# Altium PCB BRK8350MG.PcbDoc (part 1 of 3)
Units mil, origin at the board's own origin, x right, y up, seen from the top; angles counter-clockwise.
Board outline 8858.27 x 5511.81 mil, 6 copper layers (L1-TOP, L2-GND, L3-PWR, L4-PWR, L5-GND, L6-BOT), stack 81.526 mil thick; 49 components, 350 nets, 1087 pads, 250 vias.
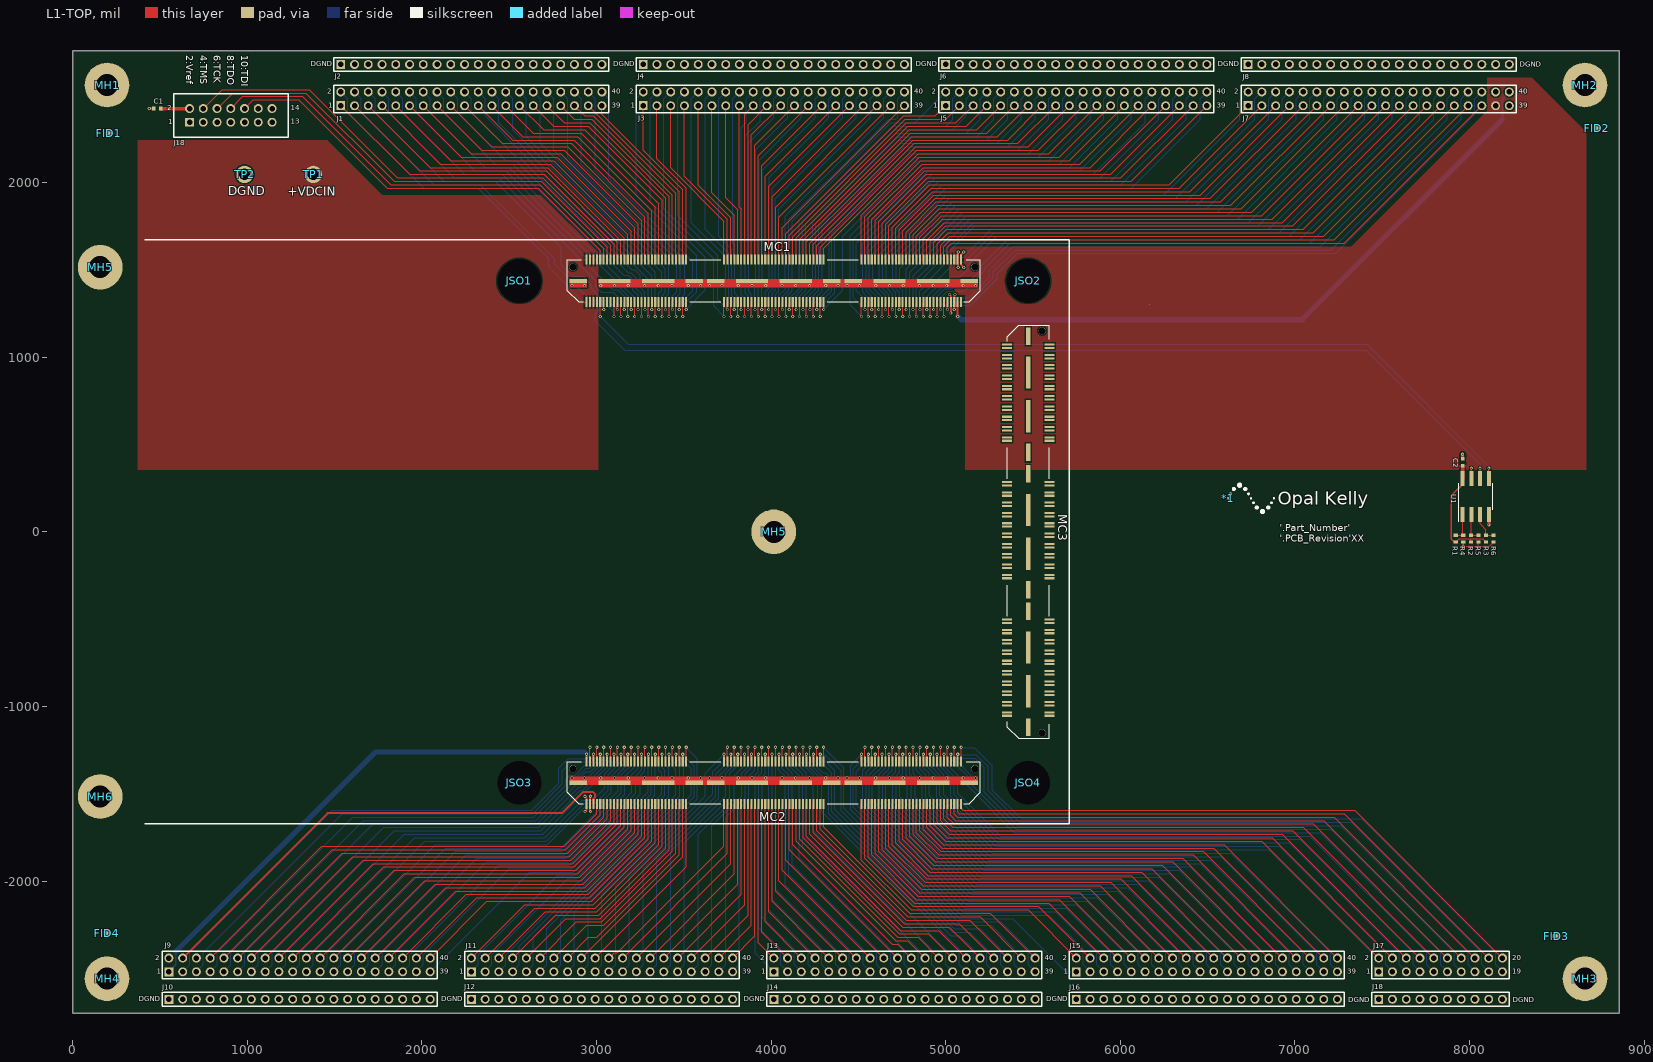
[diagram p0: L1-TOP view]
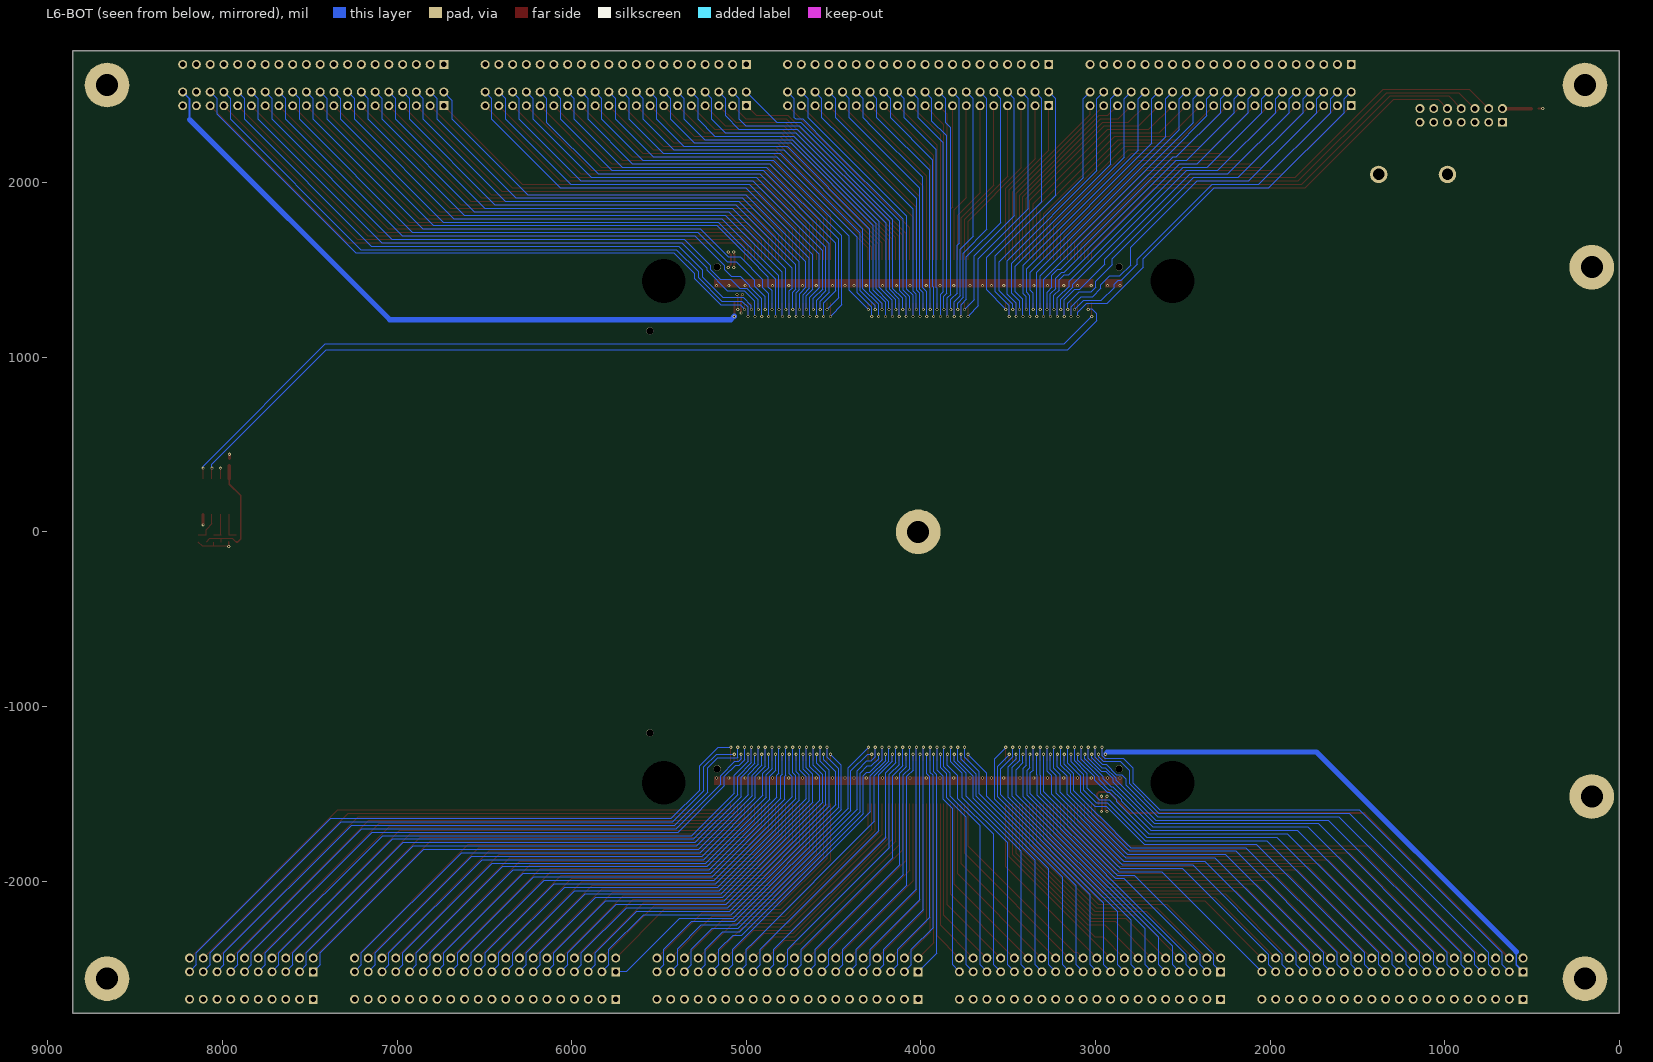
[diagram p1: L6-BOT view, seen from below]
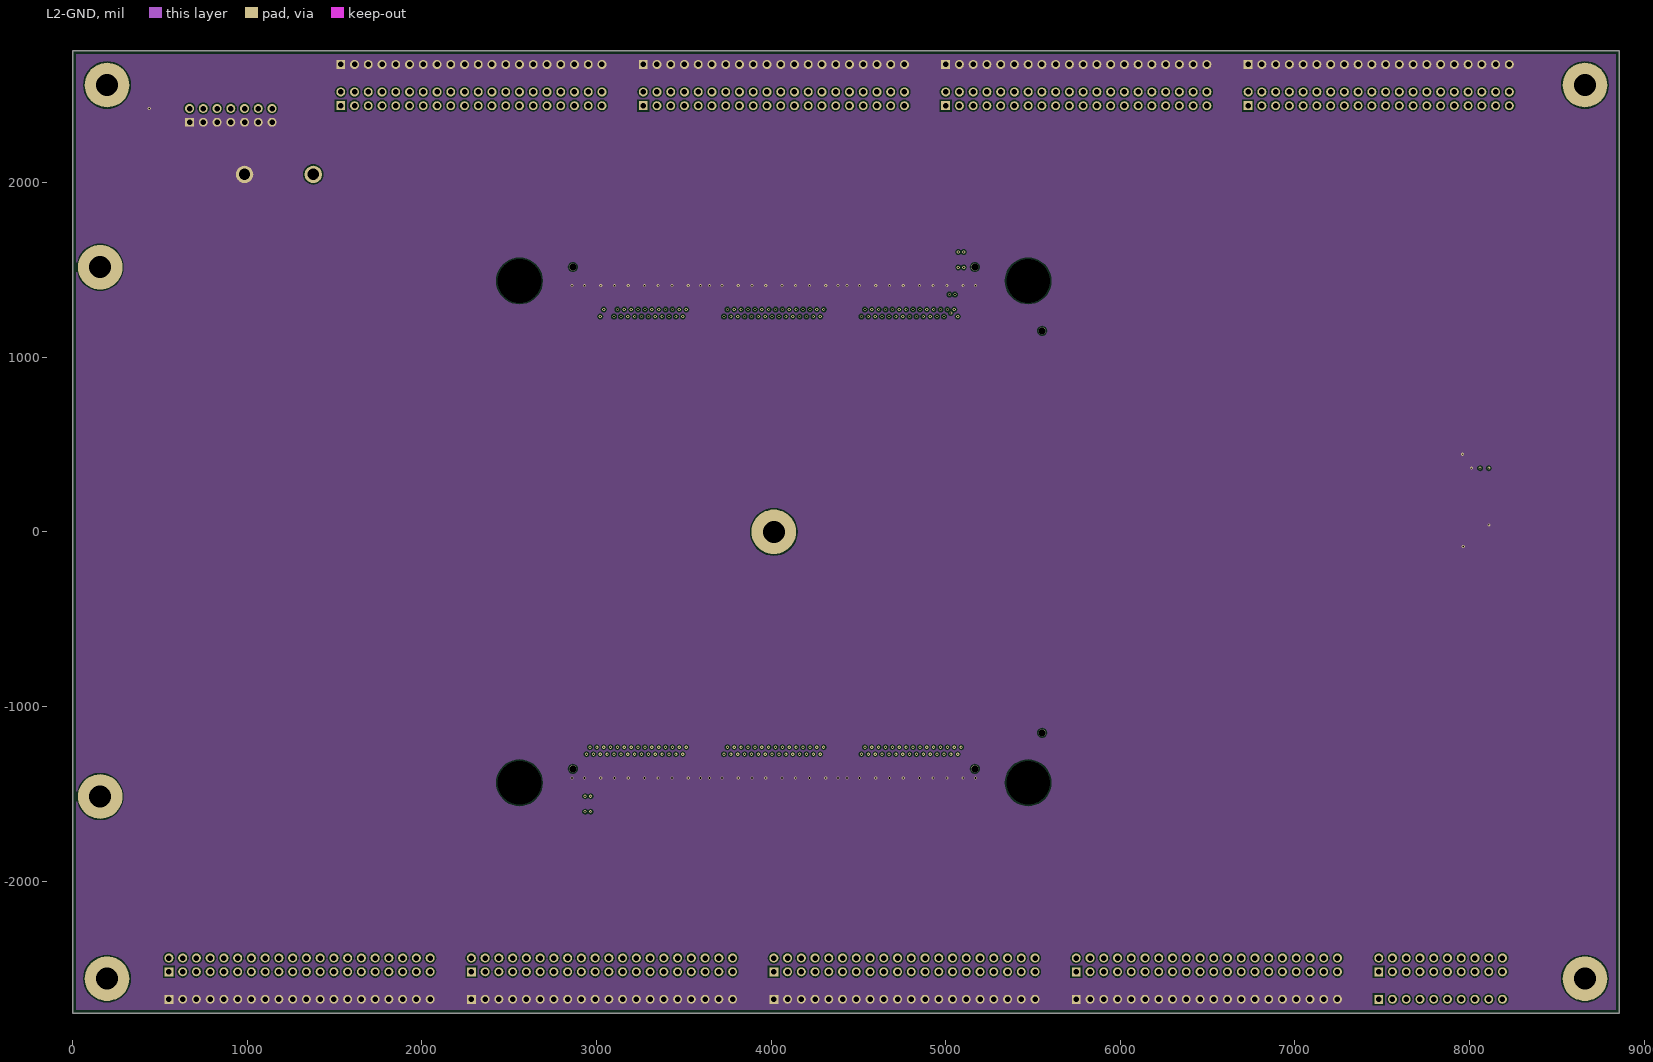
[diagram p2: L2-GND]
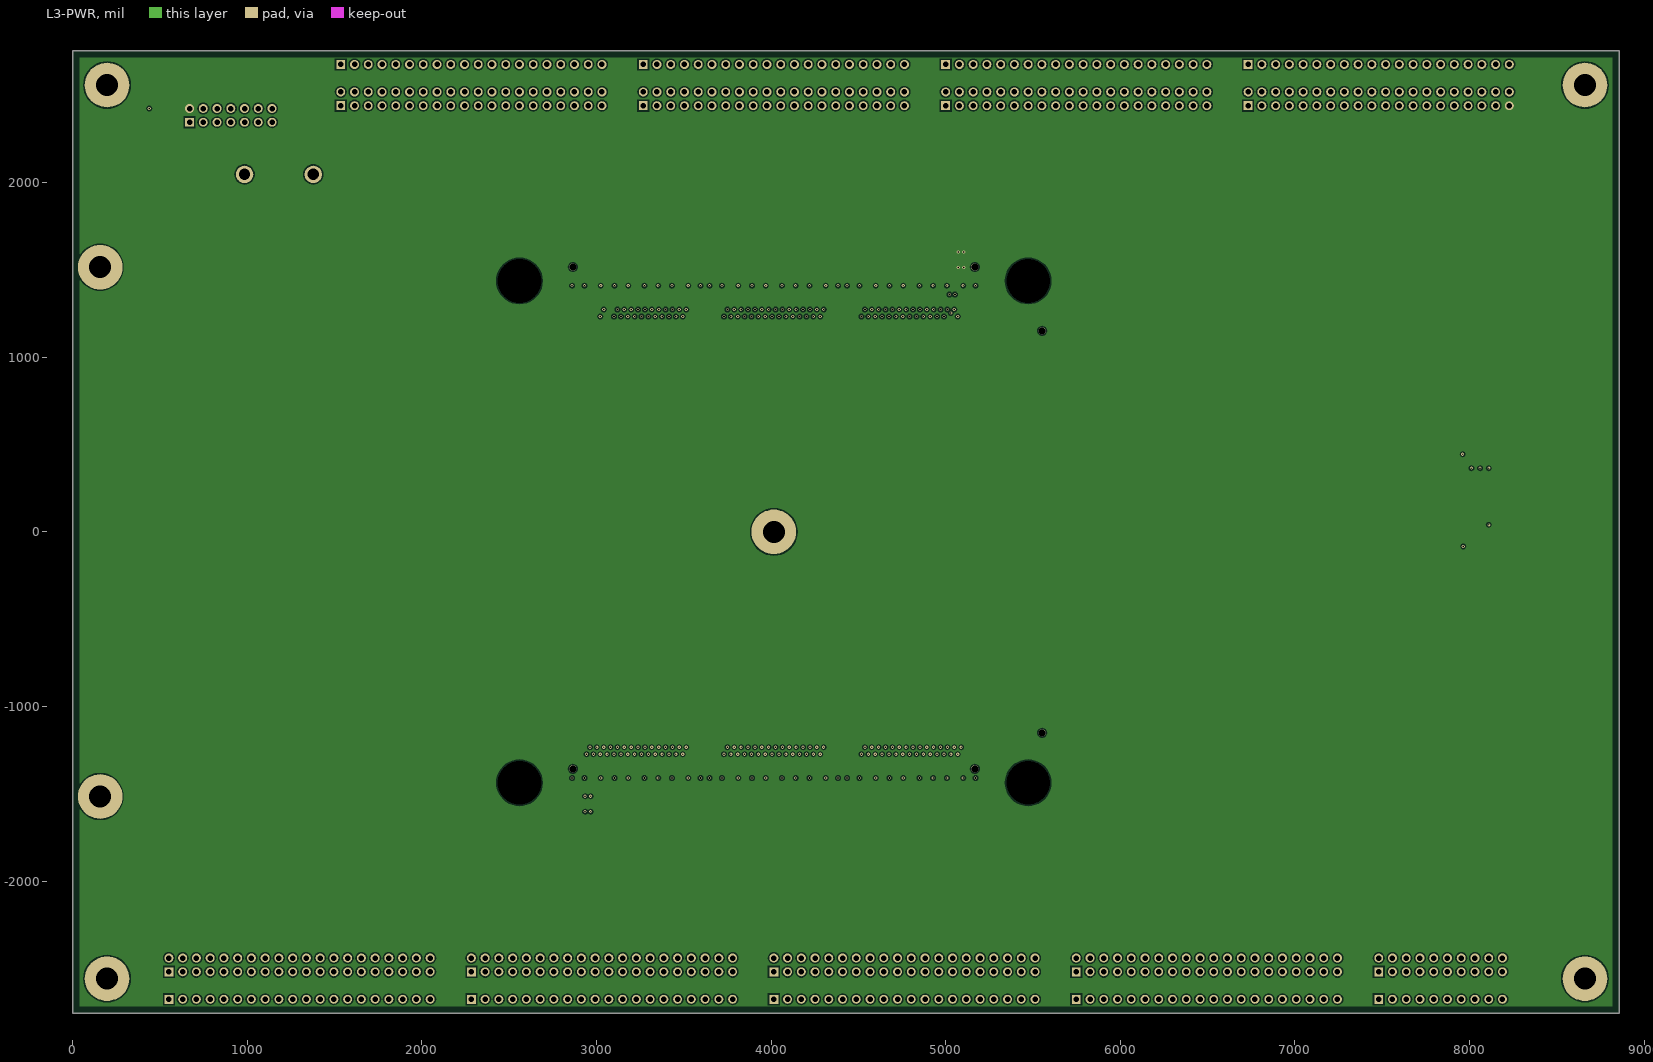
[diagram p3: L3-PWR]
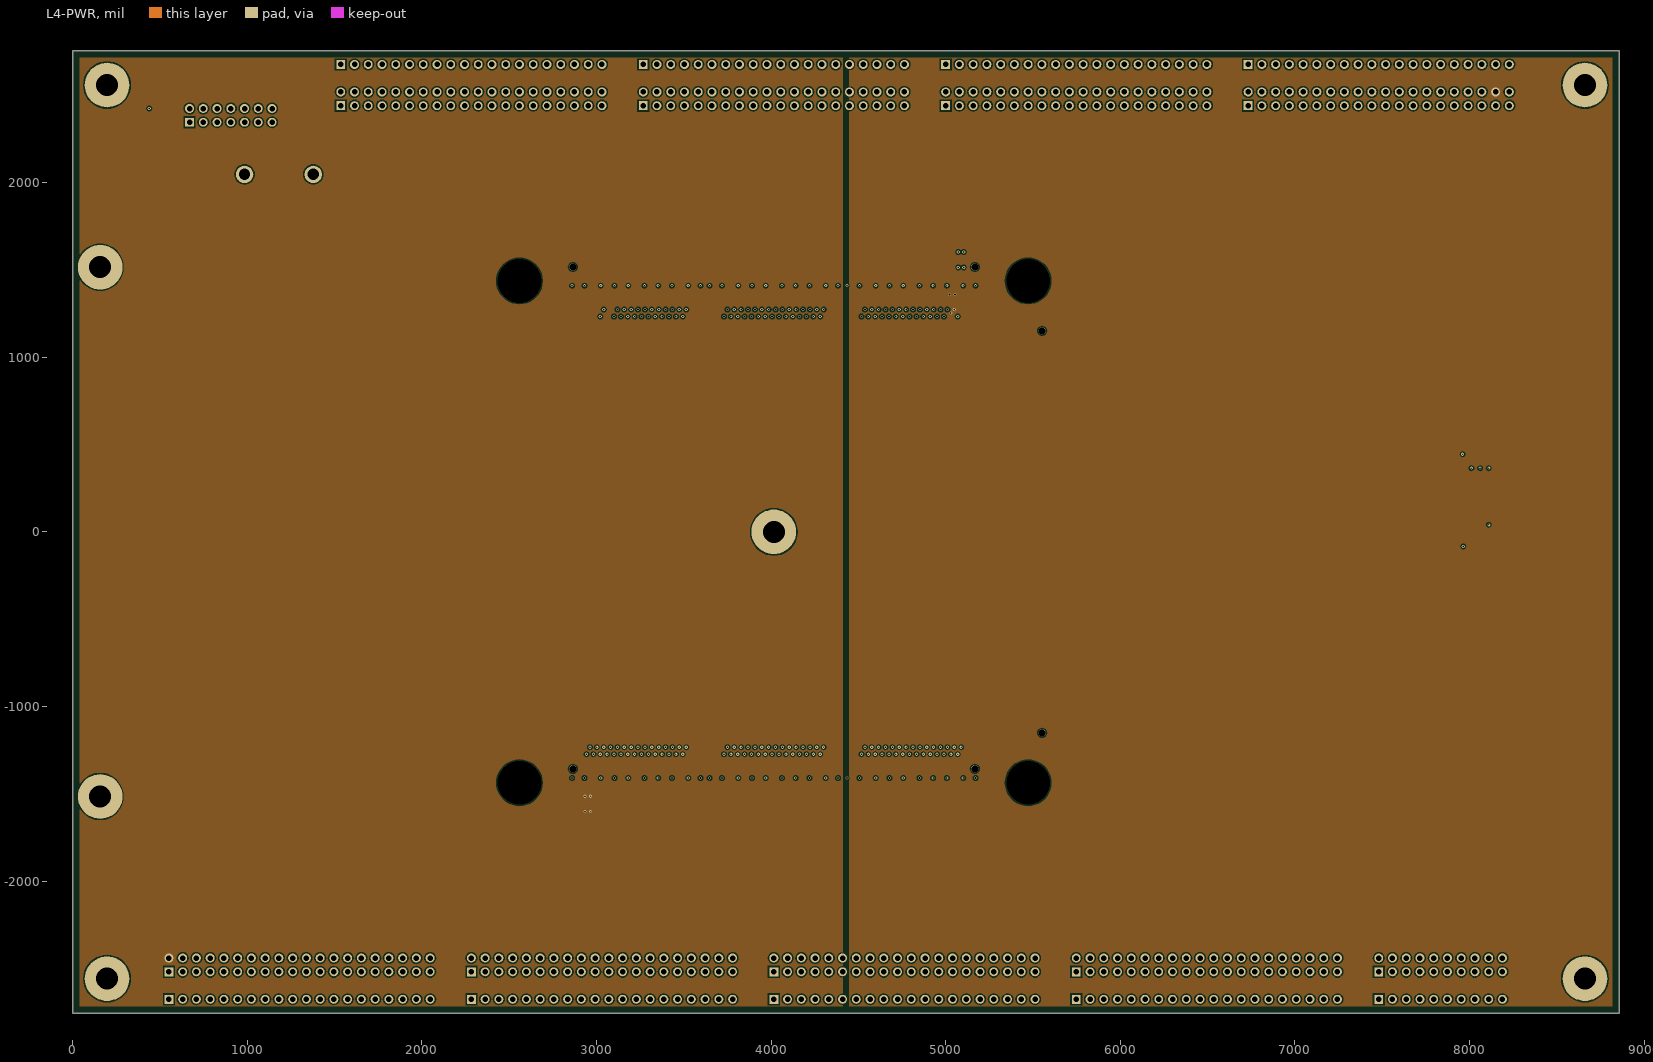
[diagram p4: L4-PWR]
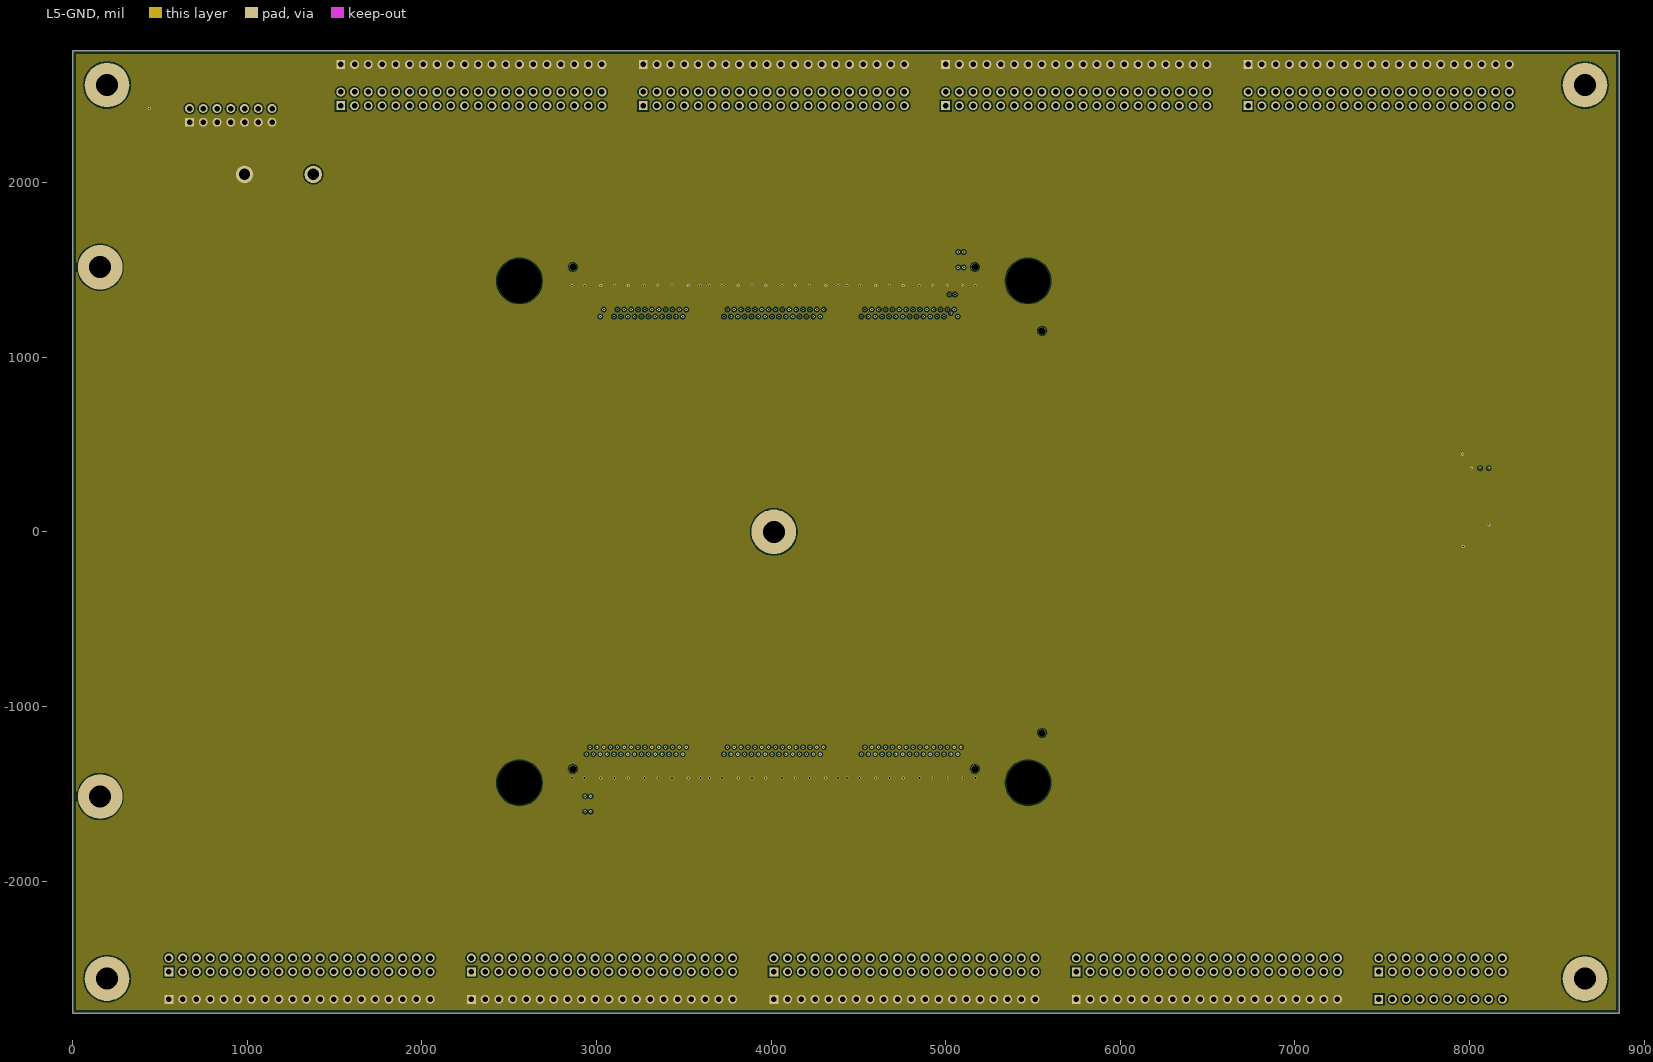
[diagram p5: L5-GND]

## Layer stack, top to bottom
Top Solder Mask: solder mask 0.8, Solder Resist, Dk 3.5
L1-TOP: signal copper 0.7
Dielectric 1-2: core 4.57, IT180A, Dk 4.07
L2-GND: signal copper 1.4
Dielectric 2: prepreg 20, IT180A, Dk 4.27
L3-PWR: signal copper 1.378
Dielectric 3: core 20, IT180A, Dk 4.02
L4-PWR: signal copper 1.378
Dielectric 1: prepreg 20, IT180A, Dk 4.27
L5-GND: signal copper 1.4
Dielectric 4: core 10, IT180A, Dk 4.07
L6-BOT: signal copper 0.7
Bottom Solder Mask: solder mask 0.8, Solder Resist, Dk 3.5

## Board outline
0,-2755.91 0,2755.91 8858.27,2755.91 8858.27,-2755.91

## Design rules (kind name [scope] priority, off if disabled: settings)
Clearance [All] p1: gap=5 ignorepadtopadclearanceinfootprint=FALSE except(4.5: SMDPad-Via Via-Via; 7: Via-Poly; 8: Arc-Poly SMDPad-Poly THPad-Poly Via-Fill Via-Region Fill-Poly Poly-Region Poly-Text Poly-Hole; 10: Track-Poly; 15: Poly-Poly)
DiffPairsRouting 100ohm_Diff [InDifferentialPairClass('100ohm_Diff')] p1: maxlimit=10 minlimit=8.4 mostfreqgap=8.4 toplayer_maxgap=8.4 toplayer_minwidth=4.2 toplayer_maxwidth=4.2 toplayer_prefwidth=4.2 midlayer1_mingap=10 midlayer1_prefgap=10 midlayer1_minwidth=15 midlayer1_maxwidth=15 midlayer1_prefwidth=15 midlayer2_maxgap=8.4 midlayer2_minwidth=4.2 midlayer2_maxwidth=4.2 midlayer2_prefwidth=4.2 midlayer3_maxgap=8.4 midlayer3_minwidth=4.2 midlayer3_maxwidth=4.2 midlayer3_prefwidth=4.2 midlayer5_mingap=10 midlayer5_prefgap=10 midlayer5_minwidth=15 midlayer5_maxwidth=15 midlayer5_prefwidth=15 bottomlayer_maxgap=8.4 bottomlayer_minwidth=4.2 bottomlayer_maxwidth=4.2 bottomlayer_prefwidth=4.2 maxuncoupledlength=350
FabricationTestPointUsage TestPointUsage [All] p1: valid=0 allowmultiple=FALSE
FabricationTestpoint Testpoint [All] p1: side=3 testpointundercomponent=TRUE minsize=40 maxsize=100 preferedsize=60 minholesize=0 maxholesize=40 preferedholesize=32 testpointgrid=1 allowsidetop=TRUE allowsidebottom=TRUE usegrid=TRUE gridtolerance=0.01
HoleSize [All] p1: absolutevalues=TRUE maxlimit=500 minlimit=8 maxpercent=80.000 minpercent=20.000
MatchedLengths okMatched_PortA [InxSignalClass('xSignals_PORTA')] p1: tolerance=1000 checknetsindiffpair=FALSE checkdiffpairvsdiffpair=TRUE checkxsignals=TRUE checkothers=TRUE
MatchedLengths okMatched_PortB [InxSignalClass('xSignals_PORTB')] p2: tolerance=1000 checknetsindiffpair=FALSE checkdiffpairvsdiffpair=TRUE checkxsignals=TRUE checkothers=TRUE
MatchedLengths okMatched_PortC [InxSignalClass('xSignals_PORTC')] p3: tolerance=1000 checknetsindiffpair=FALSE checkdiffpairvsdiffpair=TRUE checkxsignals=TRUE checkothers=TRUE
MatchedLengths okMatched_PortD [InxSignalClass('xSignals_PORTD')] p4: tolerance=1000 checknetsindiffpair=FALSE checkdiffpairvsdiffpair=TRUE checkxsignals=TRUE checkothers=TRUE
MatchedLengths okMatched_PortE [InxSignalClass('xSignals_PORTE')] p5: tolerance=1000 checknetsindiffpair=FALSE checkdiffpairvsdiffpair=TRUE checkxsignals=TRUE checkothers=TRUE
MatchedLengths okMatched_PortF [InxSignalClass('xSignals_PORTF')] p6: tolerance=1000 checknetsindiffpair=FALSE checkdiffpairvsdiffpair=TRUE checkxsignals=TRUE checkothers=TRUE
MatchedLengths okMatched_100ohm_Diff [InxSignalClass('xSignals_100ohm_Diff')] p7: tolerance=5 checknetsindiffpair=TRUE checkdiffpairvsdiffpair=FALSE checkxsignals=FALSE checkothers=FALSE
MinimumAnnularRing [All] p1: minimumring=4
MinimumSolderMaskSliver [All] p1: minsoldermaskwidth=1.9
PlaneClearance [All] p1: clearance=12
PlaneConnect [All] p1: planeconnectstyle=Direct reliefexpansion=20 reliefentries=4 reliefconductorwidth=10 reliefairgap=10
PolygonConnect "Via Connect" [IsVia] p1: connectstyle=Direct reliefconductorwidth=10 reliefentries=4 polygonreliefangle="90 Angle" airgapwidth=10
PolygonConnect [All] p2: thpad.connectstyle=Direct thpad.reliefconductorwidth=12 thpad.reliefentries=4 thpad.polygonreliefangle="90 Angle" thpad.airgapwidth=10 smdpad.connectstyle=Relief smdpad.reliefconductorwidth=12 smdpad.reliefentries=4 smdpad.polygonreliefangle="90 Angle" smdpad.airgapwidth=10 via.connectstyle=Direct via.reliefconductorwidth=12 via.reliefentries=4 via.polygonreliefangle="90 Angle" via.airgapwidth=10
RoutingVias [All] p1: holewidth=8 width=16 viastyle="Through Hole" minholewidth=8 minwidth=16 maxholewidth=50 maxwidth=100
SilkToSilkClearance [All] p1: silktosilkclearance=0.1
SilkToSolderMaskClearance SilkscreenOverComponentPads [IsPad] p1: minsilkscreentomaskgap=2 clearancetoexposedcopper=TRUE
SolderMaskExpansion [All] p1: expansion=2 istentingtop=FALSE
Width okWidth_50ohm [InNetClass('50ohm')] p1: maxlimit=10 minlimit=4.5 preferedwidth=4.6 toplayer_maxwidth=4.5 toplayer_prefwidth=4.5 midlayer1_minwidth=10 midlayer1_prefwidth=10 midlayer2_minwidth=4.6 midlayer2_maxwidth=4.6 midlayer3_minwidth=4.6 midlayer3_maxwidth=4.6 midlayer5_minwidth=10 midlayer5_prefwidth=10 bottomlayer_maxwidth=4.5 bottomlayer_prefwidth=4.5 minimp=50.000000 maximp=50.000000 favimp=50.000000
Width okWidth [All] p2: maxlimit=150 minlimit=4 preferedwidth=7.87 toplayer_prefwidth=5 midlayer1_prefwidth=5 midlayer2_prefwidth=5 midlayer3_prefwidth=5 midlayer5_minwidth=7.87 midlayer5_maxwidth=7.87 bottomlayer_prefwidth=5 minimp=50.000000 maximp=50.000000 favimp=50.000000
21 further rules are at their usual default settings.

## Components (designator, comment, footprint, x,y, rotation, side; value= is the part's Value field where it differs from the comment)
*1 "Opal Kelly Logo" okLogo-23x5 6617.7,192.24 r0 top
C1 "SM-0402, 10%, 10v" CAPC1005X06A#1 483.65,2424.44 r0 top value="0.1 u"
C2 "SM-0402, 10%, 10v" CAPC1005X06A#2 7961,399.08 r270 top value="0.1 u"
FID1 "FIDUCIAL" FID1MM/2MM-SS 207,2283 r90 top
FID2 "FIDUCIAL" FID1MM/2MM-SS 8730,2313 r90 top
FID3 "FIDUCIAL" FID1MM/2MM-SS 8496,-2316 r90 top
FID4 "FIDUCIAL" FID1MM/2MM-SS 195,-2298 r90 top
J1 "0877584016" HDR2X20-2MM 2283.46,2480.31 r0 top locked
J2 "Header, 20-Pin, Single Row" HDR1X20-2MM 2283.46,2677.17 r0 top locked
J3 "0877584016" HDR2X20-2MM 4015.75,2480.31 r0 top locked
J4 "Header, 20-Pin, Single Row" HDR1X20-2MM 4015.75,2677.17 r0 top locked
J5 "0877584016" HDR2X20-2MM 5748.03,2480.31 r0 top locked
J6 "Header, 20-Pin, Single Row" HDR1X20-2MM 5748.03,2677.17 r0 top locked
J7 "0877584016" HDR2X20-2MM 7480.31,2480.31 r0 top locked
J8 "Header, 20-Pin, Single Row" HDR1X20-2MM 7480.31,2677.17 r0 top locked
J9 "0877584016" HDR2X20-2MM 1299.21,-2480.32 r0 top locked
J10 "Header, 20-Pin, Single Row" HDR1X20-2MM 1299.21,-2677.17 r0 top locked
J11 "0877584016" HDR2X20-2MM 3031.5,-2480.32 r0 top locked
J12 "Header, 20-Pin, Single Row" HDR1X20-2MM 3031.5,-2677.17 r0 top locked
J13 "0877584016" HDR2X20-2MM 4763.78,-2480.32 r0 top locked
J14 "Header, 20-Pin, Single Row" HDR1X20-2MM 4763.78,-2677.17 r0 top locked
J15 "0877584016" HDR2X20-2MM 6496.06,-2480.32 r0 top locked
J16 "Header, 20-Pin, Single Row" HDR1X20-2MM 6496.06,-2677.17 r0 top locked
J17 "0877582016" HDR2X10-2MM 7834.65,-2480.32 r0 top locked
J18 "Header, 20-Pin, Single Row" HDR1X10-2MM 7834.65,-2677.17 r0 top locked
J18 "87831-1420" XILINX-JTAG 905.51,2385.31 r0 top
JSO1 "Jack Screw Standoff" JSO-0515-01 2559.06,1437.01 r0 top locked
JSO2 "Jack Screw Standoff" JSO-0515-01 5472.44,1437.01 r0 top locked
JSO3 "Jack Screw Standoff" JSO-0515-01 2559.06,-1437.01 r0 top locked
JSO4 "Jack Screw Standoff" JSO-0515-01 5472.44,-1437.01 r0 top locked
MC1 "QTH-090-01-F-D-A" QTH-090-01-X-D 4015.76,1437.02 r0 top locked
MC2 "QTH-090-01-F-D-A" QTH-090-01-X-D 4015.76,-1436.99 r0 top locked
MC3 "QTH-060-01-L-D-DP-A" QTH-060-01-X-D-DP-A 5472.46,0.02 r270 top locked
MH1 "MTG" MTG-3.2/6.5-PTH 196.85,2559.06 r0 top locked
MH2 "MTG" MTG-3.2/6.5-PTH 8661.42,2559.06 r0 top locked
MH3 "MTG" MTG-3.2/6.5-PTH 8661.42,-2559.06 r0 top locked
MH4 "MTG" MTG-3.2/6.5-PTH 196.85,-2559.06 r0 top locked
MH5 "MTG" MTG-3.2/6.5-PTH 4015.75,0 r0 top locked
MH5 "MTG" MTG-3.2/6.5-PTH 157.48,1515.75 r0 top locked
MH6 "MTG" MTG-3.2/6.5-PTH 157.48,-1515.75 r0 top locked
R1 "SM-0402, 1%, 1/16W" RESC1005X06A 7921.22,-38.49 r270 top value="10.0 k"
R2 "SM-0402, 1%, 1/16W" RESC1005X06A 8007.83,-38.49 r270 top value="10.0 k"
R3 "SM-0402, 1%, 1/16W" RESC1005X06A 8094.45,-38.49 r270 top value="10.0 k"
R4 "SM-0402, 1%, 1/16W" RESC1005X06A 7964.53,-38.49 r90 top value="10.0 k"
R5 "SM-0402, 1%, 1/16W" RESC1005X06A 8051.14,-38.49 r90 top value="10.0 k"
R6 "SM-0402, 1%, 1/16W" RESC1005X06A 8137.76,-38.49 r90 top value="10.0 k"
TP1 "+VDCIN" TP-PTH-65/100 1377.95,2047.24 r0 top
TP2 "DGND" TP-PTH-65/100 984.25,2047.24 r90 top
U1 "24FC256-I/SN" SO-G8 8035.96,202.42 r0 top locked

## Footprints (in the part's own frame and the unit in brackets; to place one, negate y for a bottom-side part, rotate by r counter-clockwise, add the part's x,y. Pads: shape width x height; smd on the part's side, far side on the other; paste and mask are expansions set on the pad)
CAPC1005X06A#1 [mm] "Chip Capacitor, 2-Leads, Body 1.00x0.50mm, OK custom footprint"
  rect 0.52x0.55 smd: 1(-0.51,0) 2(0.51,0)
CAPC1005X06A#2 [mm] "Chip Capacitor, 2-Leads, Body 1.00x0.50mm, OK custom footprint"
  rect 0.52x0.55 smd mask+0.051: 1(-0.51,0) 2(0.51,0)
FID1MM/2MM-SS [mm] "Fiducial 1mm copper, 2mm soldermask, single-side"
  round 1 smd paste-0.5 mask+0.5: FID?(0,0)
HDR1X10-2MM [mm] "2mm 1x20 Header"
  rect 1.3x1.3 hole 0.8: 1(-9,0)
  round 1.3 hole 0.8: 2(-7,0) 3(-5,0) 4(-3,0) 5(-1,0) 6(1,0) 7(3,0) 8(5,0) 9(7,0) 10(9,0)
  silkscreen extent -10,-1 10,1
HDR1X20-2MM [mm] "2mm 1x20 Header"
  rect 1.3x1.3 hole 0.8: 1(-19,0)
  round 1.3 hole 0.8: 2(-17,0) 3(-15,0) 4(-13,0) 5(-11,0) 6(-9,0) 7(-7,0) 8(-5,0) 9(-3,0) 10(-1,0) 11(1,0) 12(3,0) 13(5,0) 14(7,0) 15(9,0) 16(11,0) 17(13,0) 18(15,0) 19(17,0) 20(19,0)
  silkscreen extent -20,-1 20,1
HDR2X10-2MM [mm] "2mm 2x10 header"
  rect 1.3x1.3 hole 0.8: 1(-9,-1)
  round 1.3 hole 0.8: 2(-9,1) 3(-7,-1) 4(-7,1) 5(-5,-1) 6(-5,1) 7(-3,-1) 8(-3,1) 9(-1,-1) 10(-1,1) 11(1,-1) 12(1,1) 13(3,-1) 14(3,1) 15(5,-1) 16(5,1) 17(7,-1) 18(7,1) 19(9,-1) 20(9,1)
  silkscreen extent -10,-2 10,2
HDR2X20-2MM [mm] "2mm 2x20 header"
  rect 1.3x1.3 hole 0.8: 1(-19,-1)
  round 1.3 hole 0.8: 2(-19,1) 3(-17,-1) 4(-17,1) 5(-15,-1) 6(-15,1) 7(-13,-1) 8(-13,1) 9(-11,-1) 10(-11,1) 11(-9,-1) 12(-9,1) 13(-7,-1) 14(-7,1) 15(-5,-1) 16(-5,1) 17(-3,-1) 18(-3,1) 19(-1,-1) 20(-1,1) 21(1,-1) 22(1,1) 23(3,-1) 24(3,1) 25(5,-1) 26(5,1) 27(7,-1) 28(7,1) 29(9,-1) 30(9,1) 31(11,-1) 32(11,1) 33(13,-1) 34(13,1) 35(15,-1) 36(15,1) 37(17,-1) 38(17,1) 39(19,-1) 40(19,1)
  silkscreen extent -20,-2 20,2
JSO-0515-01 [mil]
  round 0 hole 250 unplated: 1(0,0)
MTG-3.2/6.5-PTH [mm] "Mounting hole, 3.2mm ID, 6.5mm OD, plated"
  round 6.5 hole 3.2: 1(0,0)
okLogo-23x5 [mil] "Opal Kelly silkscreen logo (23mm x 5mm)"
  silkscreen extent -3,-82 266,82
QTH-060-01-X-D-DP-A [mm]
  rect 2.54x0.64 smd: 0(-28.445,0) 0(-11.555,0) 0(-8.445,0) 0(8.445,0) 0(11.555,0) 0(28.445,0)
  rect 4.7x0.64 smd: 0(-23.175,0) 0(-16.825,0) 0(-3.175,0) 0(3.175,0) 0(16.825,0) 0(23.175,0)
  rect 0.3x1.45 smd: 1(-27.25,3.09) 2(-27.25,-3.09) 3(-26.75,3.09) 4(-26.75,-3.09) 5(-25.75,3.09) 6(-25.75,-3.09) 7(-25.25,3.09) 8(-25.25,-3.09) 9(-24.25,3.09) 10(-24.25,-3.09) 11(-23.75,3.09) 12(-23.75,-3.09) 13(-22.75,3.09) 14(-22.75,-3.09) 15(-22.25,3.09) 16(-22.25,-3.09) 17(-21.25,3.09) 18(-21.25,-3.09) 19(-20.75,3.09) 20(-20.75,-3.09) 21(-19.75,3.09) 22(-19.75,-3.09) 23(-19.25,3.09) 24(-19.25,-3.09) 25(-18.25,3.09) 26(-18.25,-3.09) 27(-17.75,3.09) 28(-17.75,-3.09) 29(-16.75,3.09) 30(-16.75,-3.09) 31(-16.25,3.09) 32(-16.25,-3.09) 33(-15.25,3.09) 34(-15.25,-3.09) 35(-14.75,3.09) 36(-14.75,-3.09) 37(-13.75,3.09) 38(-13.75,-3.09) 39(-13.25,3.09) 40(-13.25,-3.09) 41(-7.25,3.09) 42(-7.25,-3.09) 43(-6.75,3.09) 44(-6.75,-3.09) 45(-5.75,3.09) 46(-5.75,-3.09) 47(-5.25,3.09) 48(-5.25,-3.09) 49(-4.25,3.09) 50(-4.25,-3.09) 51(-3.75,3.09) 52(-3.75,-3.09) 53(-2.75,3.09) 54(-2.75,-3.09) 55(-2.25,3.09) 56(-2.25,-3.09) 57(-1.25,3.09) 58(-1.25,-3.09) 59(-0.75,3.09) 60(-0.75,-3.09) 61(0.25,3.09) 62(0.25,-3.09) 63(0.75,3.09) 64(0.75,-3.09) 65(1.75,3.09) 66(1.75,-3.09) 67(2.25,3.09) 68(2.25,-3.09) 69(3.25,3.09) 70(3.25,-3.09) 71(3.75,3.09) 72(3.75,-3.09) 73(4.75,3.09) 74(4.75,-3.09) 75(5.25,3.09) 76(5.25,-3.09) 77(6.25,3.09) 78(6.25,-3.09) 79(6.75,3.09) 80(6.75,-3.09) 81(12.75,3.09) 82(12.75,-3.09) 83(13.25,3.09) 84(13.25,-3.09) 85(14.25,3.09) 86(14.25,-3.09) 87(14.75,3.09) 88(14.75,-3.09) 89(15.75,3.09) 90(15.75,-3.09) 91(16.25,3.09) 92(16.25,-3.09) 93(17.25,3.09) 94(17.25,-3.09) 95(17.75,3.09) 96(17.75,-3.09) 97(18.75,3.09) 98(18.75,-3.09) 99(19.25,3.09) 100(19.25,-3.09) 101(20.25,3.09) 102(20.25,-3.09) 103(20.75,3.09) 104(20.75,-3.09) 105(21.75,3.09) 106(21.75,-3.09) 107(22.25,3.09) 108(22.25,-3.09) 109(23.25,3.09) 110(23.25,-3.09) 111(23.75,3.09) 112(23.75,-3.09) 113(24.75,3.09) 114(24.75,-3.09) 115(25.25,3.09) 116(25.25,-3.09) 117(26.25,3.09) 118(26.25,-3.09) 119(26.75,3.09) 120(26.75,-3.09)
  round 1.02 hole 1.02 unplated: MH(-29.24,2.03) MH(29.24,2.03)
  silkscreen extent -30.05,-3.05 30.05,3.05
QTH-090-01-X-D [mm]
  rect 2.54x0.64 smd: 0(-28.445,0) 0(-11.555,0) 0(-8.445,0) 0(8.445,0) 0(11.555,0) 0(28.445,0)
  rect 4.7x0.64 smd: 0(-23.175,0) 0(-16.825,0) 0(-3.175,0) 0(3.175,0) 0(16.825,0) 0(23.175,0)
  rect 0.3x1.45 smd: 1(-27.25,3.09) 2(-27.25,-3.09) 3(-26.75,3.09) 4(-26.75,-3.09) 5(-26.25,3.09) 6(-26.25,-3.09) 7(-25.75,3.09) 8(-25.75,-3.09) 9(-25.25,3.09) 10(-25.25,-3.09) 11(-24.75,3.09) 12(-24.75,-3.09) 13(-24.25,3.09) 14(-24.25,-3.09) 15(-23.75,3.09) 16(-23.75,-3.09) 17(-23.25,3.09) 18(-23.25,-3.09) 19(-22.75,3.09) 20(-22.75,-3.09) 21(-22.25,3.09) 22(-22.25,-3.09) 23(-21.75,3.09) 24(-21.75,-3.09) 25(-21.25,3.09) 26(-21.25,-3.09) 27(-20.75,3.09) 28(-20.75,-3.09) 29(-20.25,3.09) 30(-20.25,-3.09) 31(-19.75,3.09) 32(-19.75,-3.09) 33(-19.25,3.09) 34(-19.25,-3.09) 35(-18.75,3.09) 36(-18.75,-3.09) 37(-18.25,3.09) 38(-18.25,-3.09) 39(-17.75,3.09) 40(-17.75,-3.09) 41(-17.25,3.09) 42(-17.25,-3.09) 43(-16.75,3.09) 44(-16.75,-3.09) 45(-16.25,3.09) 46(-16.25,-3.09) 47(-15.75,3.09) 48(-15.75,-3.09) 49(-15.25,3.09) 50(-15.25,-3.09) 51(-14.75,3.09) 52(-14.75,-3.09) 53(-14.25,3.09) 54(-14.25,-3.09) 55(-13.75,3.09) 56(-13.75,-3.09) 57(-13.25,3.09) 58(-13.25,-3.09) 59(-12.75,3.09) 60(-12.75,-3.09) 61(-7.25,3.09) 62(-7.25,-3.09) 63(-6.75,3.09) 64(-6.75,-3.09) 65(-6.25,3.09) 66(-6.25,-3.09) 67(-5.75,3.09) 68(-5.75,-3.09) 69(-5.25,3.09) 70(-5.25,-3.09) 71(-4.75,3.09) 72(-4.75,-3.09) 73(-4.25,3.09) 74(-4.25,-3.09) 75(-3.75,3.09) 76(-3.75,-3.09) 77(-3.25,3.09) 78(-3.25,-3.09) 79(-2.75,3.09) 80(-2.75,-3.09) 81(-2.25,3.09) 82(-2.25,-3.09) 83(-1.75,3.09) 84(-1.75,-3.09) 85(-1.25,3.09) 86(-1.25,-3.09) 87(-0.75,3.09) 88(-0.75,-3.09) 89(-0.25,3.09) 90(-0.25,-3.09) 91(0.25,3.09) 92(0.25,-3.09) 93(0.75,3.09) 94(0.75,-3.09) 95(1.25,3.09) 96(1.25,-3.09) 97(1.75,3.09) 98(1.75,-3.09) 99(2.25,3.09) 100(2.25,-3.09) 101(2.75,3.09) 102(2.75,-3.09) 103(3.25,3.09) 104(3.25,-3.09) 105(3.75,3.09) 106(3.75,-3.09) 107(4.25,3.09) 108(4.25,-3.09) 109(4.75,3.09) 110(4.75,-3.09) 111(5.25,3.09) 112(5.25,-3.09) 113(5.75,3.09) 114(5.75,-3.09) 115(6.25,3.09) 116(6.25,-3.09) 117(6.75,3.09) 118(6.75,-3.09) 119(7.25,3.09) 120(7.25,-3.09) 121(12.75,3.09) 122(12.75,-3.09) 123(13.25,3.09) 124(13.25,-3.09) 125(13.75,3.09) 126(13.75,-3.09) 127(14.25,3.09) 128(14.25,-3.09) 129(14.75,3.09) 130(14.75,-3.09) 131(15.25,3.09) 132(15.25,-3.09) 133(15.75,3.09) 134(15.75,-3.09) 135(16.25,3.09) 136(16.25,-3.09) 137(16.75,3.09) 138(16.75,-3.09) 139(17.25,3.09) 140(17.25,-3.09) 141(17.75,3.09) 142(17.75,-3.09) 143(18.25,3.09) 144(18.25,-3.09) 145(18.75,3.09) 146(18.75,-3.09) 147(19.25,3.09) 148(19.25,-3.09) 149(19.75,3.09) 150(19.75,-3.09) 151(20.25,3.09) 152(20.25,-3.09) 153(20.75,3.09) 154(20.75,-3.09) 155(21.25,3.09) 156(21.25,-3.09) 157(21.75,3.09) 158(21.75,-3.09) 159(22.25,3.09) 160(22.25,-3.09) 161(22.75,3.09) 162(22.75,-3.09) 163(23.25,3.09) 164(23.25,-3.09) 165(23.75,3.09) 166(23.75,-3.09) 167(24.25,3.09) 168(24.25,-3.09) 169(24.75,3.09) 170(24.75,-3.09) 171(25.25,3.09) 172(25.25,-3.09) 173(25.75,3.09) 174(25.75,-3.09) 175(26.25,3.09) 176(26.25,-3.09) 177(26.75,3.09) 178(26.75,-3.09) 179(27.25,3.09) 180(27.25,-3.09)
  round 1.02 hole 1.02 unplated: MH(-29.24,2.03) MH(29.24,2.03)
  silkscreen extent -30.05,-3.05 30.05,3.05
RESC1005X06A [mm] "Chip Resistor, 2-Leads, Body 1.00x0.50mm, OK custom footprint"
  rect 0.5x0.6 smd mask+0.051: 1(-0.5,0) 2(0.5,0)
SO-G8 [mm] "Small Outline; 8 Leads; Body Width 3.9 mm; Pitch 1.27 mm"
  rect 0.6x2.2 smd: 1(-1.905,-2.6) 2(-0.635,-2.6) 3(0.635,-2.6) 4(1.905,-2.6) 5(1.905,2.6) 6(0.635,2.6) 7(-0.635,2.6) 8(-1.905,2.6)
  silkscreen extent -2.45,-3.7 2.45,1.95
TP-PTH-65/100 [mil] "Test point, plated through-hole, 65/100mil"
  round 100 hole 65: 1(0,0)
XILINX-JTAG [mm] "2mm 2x7 header"
  rect 1.3x1.3 hole 0.8: 1(-6,-1)
  round 1.3 hole 0.8: 2(-6,1) 3(-4,-1) 4(-4,1) 5(-2,-1) 6(-2,1) 7(0,-1) 8(0,1) 9(2,-1) 10(2,1) 11(4,-1) 12(4,1) 13(6,-1) 14(6,1)
  silkscreen extent -8.32,-3.15 8.32,3.15

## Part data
*1: library part OKLOGO, PartNumber=ALIGNI_IGNORE
C1: library part 000070, Manufacturer=Kemet, Manufacturer_PN=C0402C104K8PACTU, ValueFloat=1E-7, x_tolerance=10
C2: library part 000070, Manufacturer=Kemet, Manufacturer_PN=C0402C104K8PACTU, ValueFloat=1E-7, x_max_operating_temp=85, x_min_operating_temp=-55, x_tolerance=10
FID1 FID2 FID3 FID4: "PCB fiducial", PartNumber=ALIGNI_IGNORE
J1 J3 J5 J7 J9 J11 J13 J15: library part 000583, Manufacturer=Molex
J2 J4 J6 J8 J10 J12 J14 J16: library part 001334, Manufacturer=3M, Manufacturer_PN=951120-8622-AR
J17: library part 001338, Manufacturer=Molex
J18: library part 002002, Manufacturer=3M, Manufacturer_PN=951110-8622-AR
J18: library part 000541, "2mm header, shrouded", Manufacturer=Molex
JSO1 JSO2 JSO3 JSO4: library part 001879, "Mounting hole", Manufacturer=Samtec, Manufacturer_PN=JSO-0515-01
MC1 MC2: library part 000876, "0.5mm Double Row High Speed Socket Assembly", Manufacturer=Samtec
MC3: library part 001769, Manufacturer=Samtec
MH1 MH2 MH3 MH4 MH5 MH5 MH6: "Mounting hole", PartNumber=ALIGNI_IGNORE
R1 R2 R3 R4 R5 R6: library part 001521, Manufacturer=Vishay, Manufacturer_PN=CRCW040210K0FKED, ValueFloat=10000, x_tolerance=1
TP1 TP2: library part TP-PTH-65/100, "Test point, plated through-hole, 65/100mil", PartNumber=ALIGNI_IGNORE
U1: library part 000842, Manufacturer=Microchip

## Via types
v1: diameter 18, hole 10, L1-TOP to L6-BOT, tented both sides, 250 vias

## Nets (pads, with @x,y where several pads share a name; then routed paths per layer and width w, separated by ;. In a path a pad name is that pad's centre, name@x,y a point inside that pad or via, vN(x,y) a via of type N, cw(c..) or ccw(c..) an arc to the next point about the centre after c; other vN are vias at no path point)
+1.8VDD: C1.2 J7.39 J18.2@669.29,2424.69 MC1.177 MC1.179 | length 356.5
  L1-TOP w11: v1(5071.85,1514.68) 5071.85,1527.15 5068.91,1530.09 MC1.177@5068.91,1558.68 5068.91,1587.91 5071.85,1590.85 v1(5071.85,1602.68) ; v1(5103.6,1514.68) 5088.6,1529.68 MC1.179@5088.6,1558.68 5088.6,1587.68 v1(5103.6,1602.68)
  L1-TOP w20: C1.2@503.73,2424.44 669.04,2424.44 J18.2@669.29,2424.69
+3.3VDD: C2.2 J7.37 MC1.173 MC1.175 R1.2 R2.2 R3.2 U1.8 | length 687.5
  L1-TOP w5: R1.2@7921.22,-58.17 7940.39,-39 8007.83,-39 ; R2.2@8007.83,-58.17 8007.83,-39 ; R3.2@8094.45,-58.17 8075.28,-39 8007.83,-39
  L1-TOP w10: R1.2@7921.22,-58.17 7913.17,-58.17 7896,-41 7896,208 7960.96,272.96 U1.8@7960.96,304.78
  L1-TOP w20: U1.8@7960.96,304.78 7961,304.82 C2.2@7961,379
+VDCIN: MC1.1 MC1.2 MC1.3 MC1.4 MC1.5 MC1.6 MC1.7 MC1.8 TP1.1
B24_L1N: J15.8 MC2.128 | length 1943.8
  L1-TOP w5: MC2.128@4576.79,-1558.65 4576.79,-1850.41 4832.68,-2106.3 5649.61,-2106.3 J15.8@5984.25,-2440.94
B24_L1P: J15.6 MC2.126 | length 1890.5
  L1-TOP w5: MC2.126@4557.1,-1558.65 4557.1,-1860.25 4822.83,-2125.98 5314.96,-2125.98 5590.55,-2125.98 J15.6@5905.51,-2440.94
B24_L2N: J11.37 MC2.77 | length 1361.8
  L1-TOP w5: MC2.77@3887.81,-1313.34 v1(3887.81,-1273.34)
  L6-BOT w5: J11.37@3700.79,-2519.69 3740.16,-2480.31 3740.16,-1633.86 3851.79,-1522.22 3851.79,-1386.21 3887.81,-1350.19 v1@3887.81,-1275.34
B24_L2P: J11.35 MC2.75 | length 1466.3
  L1-TOP w5: MC2.75@3868.13,-1313.34 v1(3868.13,-1233.34)
  L6-BOT w5: J11.35@3622.05,-2519.69 3661.42,-2480.31 3661.42,-1683.07 3831.22,-1513.27 3831.22,-1382.78 3868.13,-1345.87 v1@3868.13,-1235.34
B24_L3N: J13.18 MC2.98 | length 1114.7
  L1-TOP w5: MC2.98@4084.66,-1558.65 4084.66,-1879.94 4606.3,-2401.57 J13.18@4645.67,-2440.95
B24_L3P: J13.16 MC2.96 | length 1090.2
  L1-TOP w5: MC2.96@4064.98,-1558.65 4064.98,-1938.99 J13.16@4566.93,-2440.95
B24_L4N: J13.13 MC2.93 | length 1467.8
  L1-TOP w5: MC2.93@4045.29,-1313.34 v1(4045.29,-1273.34)
  L6-BOT w5: v1@4045.29,-1275.34 4045.29,-1364.92 4080,-1399.63 4080,-2022.91 4448.82,-2391.73 4448.82,-2480.32 J13.13@4488.19,-2519.69
B24_L4P: J13.11 MC2.91 | length 1523.3
  L1-TOP w5: MC2.91@4025.61,-1313.34 v1(4025.61,-1233.34)
  L6-BOT w5: v1@4025.61,-1235.34 4025.61,-2047.26 4370.08,-2391.73 4370.08,-2480.32 J13.11@4409.45,-2519.69
B24_L5N: J15.3 MC2.123 | length 2247.5
  L1-TOP w5: MC2.123@4537.42,-1313.34 v1(4537.42,-1233.34)
  L6-BOT w5: v1@4537.42,-1235.34 4537.42,-1290.58 4471,-1357 4471,-1577.3 5088.58,-2194.88 5590.55,-2194.88 5787.4,-2391.73 5787.4,-2480.32 J15.3@5826.77,-2519.69
B24_L5P: J15.1 MC2.121 | length 2059.3
  L1-TOP w5: MC2.121@4517.73,-1313.34 v1(4517.73,-1273.34)
  L6-BOT w5: v1@4517.73,-1275.34 4455,-1338.07 4455,-1590.83 5078.74,-2214.57 5383.86,-2214.57 5688.98,-2519.69 J15.1@5748.03,-2519.69
B24_L6N: J13.17 MC2.97 | length 1516.7
  L1-TOP w5: MC2.97@4084.66,-1313.34 v1(4084.66,-1273.34)
  L6-BOT w5: v1@4084.66,-1275.34 4084.66,-1346.62 4121,-1382.96 4121,-1906.43 4606.3,-2391.73 4606.3,-2480.32 J13.17@4645.67,-2519.69
B24_L6P: J13.15 MC2.95 | length 1572.3
  L1-TOP w5: MC2.95@4064.98,-1313.34 v1(4064.98,-1233.34)
  L6-BOT w5: v1@4064.98,-1235.34 4064.98,-1356.29 4100,-1391.31 4100,-1964.17 4527.56,-2391.73 4527.56,-2480.32 J13.15@4566.93,-2519.69
B24_L7N: J13.14 MC2.94 | length 1065.8
  L1-TOP w5: MC2.94@4045.29,-1558.65 4045.29,-1998.05 J13.14@4488.19,-2440.94
B24_L7P: J13.12 MC2.92 | length 1041.3
  L1-TOP w5: MC2.92@4025.61,-1558.65 4025.61,-2057.1 4350.39,-2381.89 J13.12@4409.45,-2440.94
B24_L8N: J13.21 MC2.101 | length 1565.6
  L1-TOP w5: MC2.101@4124.03,-1313.34 v1(4124.03,-1273.34)
  L6-BOT w5: v1@4124.03,-1275.34 4124.03,-1333.03 4180,-1389 4180,-1807.95 4763.78,-2391.73 4763.78,-2480.32 J13.21@4803.15,-2519.69
B24_L8P: J13.19 MC2.99 | length 1621.2
  L1-TOP w5: MC2.99@4104.35,-1313.34 v1(4104.35,-1233.34)
  L6-BOT w5: v1@4104.35,-1235.34 4104.35,-1340.48 4160,-1396.14 4160,-1866.69 4685.04,-2391.73 4685.04,-2480.32 J13.19@4724.41,-2519.69
B24_L9N: J13.29 MC2.109 | length 1663.5
  L1-TOP w5: MC2.109@4202.77,-1313.34 v1(4202.77,-1273.34)
  L6-BOT w5: v1@4202.77,-1275.34 4202.77,-1309.77 4291,-1398 4291,-1603.99 5078.74,-2391.73 5078.74,-2480.32 J13.29@5118.11,-2519.69
B24_L9P: J13.27 MC2.107 | length 1719
  L1-TOP w5: MC2.107@4183.09,-1313.34 v1(4183.09,-1233.34)
  L6-BOT w5: v1@4183.09,-1235.34 4183.09,-1314.09 4266,-1397 4266,-1657.73 4960.63,-2352.36 5000,-2391.73 5000,-2480.32 J13.27@5039.37,-2519.69
B24_L10N: J13.1 MC2.81 | length 1335.3
  L1-TOP w5: MC2.81@3927.18,-1313.34 v1(3927.18,-1273.34)
  L6-BOT w5: v1@3927.18,-1275.34 3927.18,-1372.95 3910,-1390.13 3910,-2413.94 J13.1@4015.75,-2519.69
B24_L10P: J11.39 MC2.79 | length 1417.4
  L1-TOP w5: MC2.79@3907.5,-1313.34 v1(3907.5,-1233.34)
  L6-BOT w5: J11.39@3779.53,-2519.69 3818.9,-2480.32 3818.9,-1584.65 3872,-1531.54 3872,-1401 3907.5,-1365.5 v1@3907.5,-1235.34
B24_L11N: J13.6 MC2.86 | length 967.9
  L1-TOP w5: MC2.86@3966.55,-1558.65 3966.55,-2234.27 J13.6@4173.23,-2440.94
B24_L11P: J13.4 MC2.84 | length 943.4
  L1-TOP w5: MC2.84@3946.87,-1558.65 3946.87,-2293.32 J13.4@4094.49,-2440.94
B24_L12N: J13.5 MC2.85 | length 1383.5
  L1-TOP w5: MC2.85@3966.55,-1313.34 v1(3966.55,-1273.34)
  L6-BOT w5: v1@3966.55,-1275.34 3966.55,-1384.92 3950.18,-1401.29 3950.18,-2208.05 4133.86,-2391.73 4133.86,-2480.32 J13.5@4173.23,-2519.69
B24_L12P: J13.3 MC2.83 | length 1439.5
  L1-TOP w5: MC2.83@3946.87,-1313.34 v1(3946.87,-1233.34)
  L6-BOT w5: v1@3946.87,-1235.34 3946.87,-1378.36 3930,-1395.23 3930,-2266.61 4055.12,-2391.73 4055.12,-2480.32 J13.3@4094.49,-2519.69
B24_L13N: J13.2 MC2.82 | length 919
  L1-TOP w5: MC2.82@3927.18,-1558.65 3927.18,-2352.38 J13.2@4015.75,-2440.94
B24_L13P: J11.40 MC2.80 | length 935.3
  L1-TOP w5: J11.40@3779.53,-2440.94 3907.5,-2312.98 MC2.80@3907.5,-1558.65
B24_L14N: J13.9 MC2.89 | length 1418.9
  L1-TOP w5: MC2.89@4005.92,-1313.34 v1(4005.92,-1273.34)
  L6-BOT w5: v1@4005.92,-1275.34 4005.92,-2106.32 4291.34,-2391.73 4291.34,-2480.32 J13.9@4330.71,-2519.69
B24_L14P: J13.7 MC2.87 | length 1474.4
  L1-TOP w5: MC2.87@3986.24,-1313.34 v1(3986.24,-1233.34)
  L6-BOT w5: v1@3986.24,-1235.34 3986.24,-2165.37 4212.6,-2391.73 4212.6,-2480.32 J13.7@4251.97,-2519.69
B24_L15N: J13.10 MC2.90 | length 1016.8
  L1-TOP w5: MC2.90@4005.92,-1558.65 4005.92,-2116.16 4291.34,-2401.57 J13.10@4330.71,-2440.94
B24_L15P: J13.8 MC2.88 | length 992.4
  L1-TOP w5: MC2.88@3986.24,-1558.65 3986.24,-2175.21 4163.39,-2352.36 J13.8@4251.97,-2440.94
B24_L16N: J15.4 MC2.124 | length 1837.3
  L1-TOP w5: MC2.124@4537.42,-1558.65 4537.42,-1870.09 4812.99,-2145.67 5531.5,-2145.67 J15.4@5826.77,-2440.94
B24_L16P: J15.2 MC2.122 | length 1784
  L1-TOP w5: MC2.122@4517.73,-1558.65 4517.73,-1879.94 4803.15,-2165.35 5472.44,-2165.35 J15.2@5748.03,-2440.94
B24_L17N: J13.34 MC2.114 | length 1494.9
  L1-TOP w5: MC2.114@4242.14,-1558.65 4242.14,-1722.46 4763.78,-2244.09 5078.74,-2244.09 J13.34@5275.59,-2440.95
B24_L17P: J13.32 MC2.112 | length 1441.6
  L1-TOP w5: MC2.112@4222.46,-1558.65 4222.46,-1732.3 4753.94,-2263.78 5019.68,-2263.78 J13.32@5196.85,-2440.95
B24_L18N: J13.22 MC2.102 | length 1180.9
  L1-TOP w5: MC2.102@4124.03,-1558.65 4124.03,-1791.35 4694.88,-2362.2 4724.41,-2362.2 J13.22@4803.15,-2440.95
B24_L18P: J13.20 MC2.100 | length 1139.1
  L1-TOP w5: MC2.100@4104.35,-1558.65 4104.35,-1820.88 4665.35,-2381.89 J13.20@4724.41,-2440.95
B24_L19N: J13.33 MC2.113 | length 1782.6
  L1-TOP w5: MC2.113@4242.14,-1313.34 v1(4242.14,-1273.34)
  L6-BOT w5: v1@4242.14,-1275.34 4242.14,-1298.14 4287.82,-1343.82 4309.29,-1343.82 4348.37,-1382.9 4348.37,-1602.31 5039.37,-2293.31 5137.8,-2293.31 5236.22,-2391.73 5236.22,-2480.32 J13.33@5275.59,-2519.69
B24_L19P: J13.31 MC2.111 | length 1806.7
  L1-TOP w5: MC2.111@4222.46,-1313.34 v1(4222.46,-1233.34)
  L6-BOT w5: v1@4222.46,-1235.34 4222.46,-1304.46 4296.5,-1378.5 4313.5,-1378.5 4331.44,-1396.44 4331.44,-1614.9 5029.53,-2312.99 5078.74,-2312.99 5157.48,-2391.73 5157.48,-2480.32 J13.31@5196.85,-2519.69
B24_L20N: J13.38 MC2.118 | length 1601.4
  L1-TOP w5: MC2.118@4281.51,-1558.65 4281.51,-1702.77 4783.46,-2204.72 5196.85,-2204.72 J13.38@5433.07,-2440.95
B24_L20P: J13.36 MC2.116 | length 1548.2
  L1-TOP w5: MC2.116@4261.83,-1558.65 4261.83,-1712.61 4773.62,-2224.41 5137.8,-2224.41 J13.36@5354.33,-2440.95
B24_L21N: J13.37 MC2.117 | length 1894.2
  L1-TOP w5: MC2.117@4281.51,-1313.34 v1(4281.51,-1273.34)
  L6-BOT w5: v1@4281.51,-1275.34 4307.34,-1275.34 4401.14,-1369.14 4401.14,-1596.02 5059.06,-2253.94 5260.11,-2253.94 5393.7,-2387.53 5393.7,-2480.32 J13.37@5433.07,-2519.69
B24_L21P: J13.35 MC2.115 | length 1917.7
  L1-TOP w5: MC2.115@4261.83,-1313.34 v1(4261.83,-1233.34)
  L6-BOT w5: v1@4261.83,-1235.34 4261.83,-1287.83 4288.7,-1314.7 4313.13,-1314.7 4365.68,-1367.25 4365.68,-1590.09 5049.21,-2273.62 5196.85,-2273.62 5314.96,-2391.73 5314.96,-2480.32 J13.35@5354.33,-2519.69
B24_L22N: J13.26 MC2.106 | length 1281.7
  L1-TOP w5: MC2.106@4163.4,-1558.65 4163.4,-1761.83 4724.41,-2322.83 4842.52,-2322.83 J13.26@4960.63,-2440.95
B24_L22P: J13.24 MC2.104 | length 1228.4
  L1-TOP w5: MC2.104@4143.72,-1558.65 4143.72,-1771.67 4714.57,-2342.52 4783.46,-2342.52 J13.24@4881.89,-2440.95
B24_L23N: J13.30 MC2.110 | length 1388.3
  L1-TOP w5: MC2.110@4202.77,-1558.65 4202.77,-1742.14 4744.09,-2283.46 4960.63,-2283.46 J13.30@5118.11,-2440.95
B24_L23P: J13.28 MC2.108 | length 1335
  L1-TOP w5: MC2.108@4183.09,-1558.65 4183.09,-1751.98 4734.25,-2303.15 4901.57,-2303.15 J13.28@5039.37,-2440.95
B24_L24N: J13.25 MC2.105 | length 1614.6
  L1-TOP w5: MC2.105@4163.4,-1313.34 v1(4163.4,-1273.34)
  L6-BOT w5: v1@4163.4,-1275.34 4163.4,-1314.4 4241,-1392 4241,-1711.47 4921.26,-2391.73 4921.26,-2480.32 J13.25@4960.63,-2519.69
B24_L24P: J13.23 MC2.103 | length 1670.1
  L1-TOP w5: MC2.103@4143.72,-1313.34 v1(4143.72,-1233.34)
  L6-BOT w5: v1@4143.72,-1235.34 4143.72,-1322.72 4202,-1381 4202,-1751.21 4842.52,-2391.73 4842.52,-2480.32 J13.23@4881.89,-2519.69
B24_T0U_N12: J13.40 MC2.120 | length 1654.7
  L1-TOP w5: MC2.120@4301.2,-1558.65 4301.2,-1692.93 4793.31,-2185.04 5255.91,-2185.04 J13.40@5511.81,-2440.95
B24_T1U_N12: J13.39 MC2.119 | length 2009.9
  L1-TOP w5: MC2.119@4301.2,-1313.34 v1(4301.2,-1233.34)
  L6-BOT w5: v1@4301.2,-1235.34 4417.43,-1351.57 4417.43,-1582.79 5068.9,-2234.25 5314.96,-2234.25 5472.44,-2391.73 5472.44,-2480.32 J13.39@5511.81,-2519.69
B24_T2U_N12: J15.5 MC2.125 | length 2212.3
  L1-TOP w5: MC2.125@4557.1,-1313.34 v1(4557.1,-1273.34)
  L6-BOT w5: v1@4557.1,-1275.34 4557.1,-1304.9 4487,-1375 4487,-1563.77 5098.43,-2175.2 5629.92,-2175.2 5866.14,-2411.42 5866.14,-2480.32 J15.5@5905.51,-2519.69
B24_T3U_N12: J15.10 MC2.130 | length 1997.1
  L1-TOP w5: MC2.130@4596.47,-1558.65 4596.47,-1840.57 4842.52,-2086.61 5708.66,-2086.61 J15.10@6062.99,-2440.94
B25_L1N: J15.13 MC2.133 | length 2413.8
  L1-TOP w5: MC2.133@4635.84,-1313.34 v1(4635.84,-1273.34)
  L6-BOT w5: v1@4635.84,-1275.34 4635.84,-1344.84 4579.8,-1400.88 4579.8,-1538.46 5137.8,-2096.46 5866.14,-2096.46 6181.1,-2411.42 6181.1,-2480.32 J15.13@6220.47,-2519.69
B25_L1P: J15.11 MC2.131 | length 2439.4
  L1-TOP w5: MC2.131@4616.16,-1313.34 v1(4616.16,-1233.34)
  L6-BOT w5: v1@4616.16,-1235.34 4616.16,-1336.72 4561.51,-1391.36 4561.51,-1549.7 5127.95,-2116.14 5807.09,-2116.14 6102.36,-2411.42 6102.36,-2480.32 J15.11@6141.73,-2519.69
B25_L2N: J15.17 MC2.137 | length 2503.7
  L1-TOP w5: MC2.137@4675.21,-1313.34 v1(4675.21,-1273.34)
  L6-BOT w5: v1@4675.21,-1275.34 4675.21,-1359.36 4639.25,-1395.32 4639.25,-1538.86 5157.48,-2057.09 5984.25,-2057.09 6338.58,-2411.42 6338.58,-2480.32 J15.17@6377.95,-2519.69
B25_L2P: J15.15 MC2.135 | length 2531.4
  L1-TOP w5: MC2.135@4655.53,-1313.34 v1(4655.53,-1233.34)
  L6-BOT w5: v1@4655.53,-1235.34 4655.53,-1351.61 4618.4,-1388.73 4618.4,-1547.54 5147.64,-2076.77 5925.2,-2076.77 6259.84,-2411.42 6259.84,-2480.32 J15.15@6299.21,-2519.69
B25_L3N: J15.18 MC2.138 | length 2210.3
  L1-TOP w5: MC2.138@4675.21,-1558.65 4675.21,-1801.2 4881.89,-2007.87 5944.88,-2007.87 J15.18@6377.95,-2440.94
B25_L3P: J15.16 MC2.136 | length 2157
  L1-TOP w5: MC2.136@4655.53,-1558.65 4655.53,-1811.04 4872.05,-2027.56 5413.39,-2027.56 5885.83,-2027.56 J15.16@6299.21,-2440.94
B25_L4N: J15.34 MC2.154 | length 2636.6
  L1-TOP w5: MC2.154@4832.69,-1558.65 4832.69,-1722.46 4960.63,-1850.39 6417.32,-1850.39 J15.34@7007.87,-2440.94
B25_L4P: J15.32 MC2.152 | length 2583.3
  L1-TOP w5: MC2.152@4813.01,-1558.65 4813.01,-1732.3 4950.79,-1870.08 6358.27,-1870.08 J15.32@6929.13,-2440.94
B25_L5N: J15.14 MC2.134 | length 2103.7
  L1-TOP w5: MC2.134@4635.84,-1558.65 4635.84,-1820.88 4862.2,-2047.24 5826.77,-2047.24 J15.14@6220.47,-2440.94
B25_L5P: J15.12 MC2.132 | length 2050.4
  L1-TOP w5: MC2.132@4616.16,-1558.65 4616.16,-1830.72 4852.36,-2066.93 5767.72,-2066.93 J15.12@6141.73,-2440.94
B25_L6N: J15.22 MC2.142 | length 2316.9
  L1-TOP w5: MC2.142@4714.58,-1558.65 4714.58,-1781.51 4901.57,-1968.5 6062.99,-1968.5 J15.22@6535.43,-2440.94
B25_L6P: J15.20 MC2.140 | length 2263.6
  L1-TOP w5: MC2.140@4694.9,-1558.65 4694.9,-1791.35 4891.73,-1988.19 6003.94,-1988.19 J15.20@6456.69,-2440.94
B25_L7N: J15.40 MC2.160 | length 2796.5
  L1-TOP w5: MC2.160@4891.75,-1558.65 4891.75,-1692.93 4990.16,-1791.34 6594.49,-1791.34 J15.40@7244.09,-2440.94
B25_L7P: J15.38 MC2.158 | length 2743.2
  L1-TOP w5: MC2.158@4872.06,-1558.65 4872.06,-1702.77 4980.32,-1811.02 6535.43,-1811.02 J15.38@7165.35,-2440.94
B25_L8N: J15.39 MC2.159 | length 3140.1
  L1-TOP w5: MC2.159@4891.75,-1313.34 v1(4891.75,-1233.34)
  L6-BOT w5: v1@4891.75,-1235.34 4891.75,-1342.75 4949.36,-1400.36 4949.36,-1524.16 5265.75,-1840.55 6633.86,-1840.55 7204.72,-2411.42 7204.72,-2480.32 J15.39@7244.09,-2519.69
B25_L8P: J15.37 MC2.157 | length 3006.9
  L1-TOP w5: MC2.157@4872.06,-1313.34 v1(4872.06,-1273.34)
  L6-BOT w5: v1@4872.06,-1275.34 4872.06,-1350.94 4905,-1383.88 4905,-1509.33 5255.91,-1860.24 6574.8,-1860.24 7125.98,-2411.42 7125.98,-2480.32 J15.37@7165.35,-2519.69
B25_L9N: J15.35 MC2.155 | length 3033.6
  L1-TOP w5: MC2.155@4852.38,-1313.34 v1(4852.38,-1233.34)
  L6-BOT w5: v1@4852.38,-1235.34 4852.38,-1357.6 4886,-1391.22 4886,-1519.86 5246.06,-1879.92 6515.75,-1879.92 7047.24,-2411.42 7047.24,-2480.32 J15.35@7086.61,-2519.69
B25_L9P: J15.33 MC2.153 | length 2900.3
  L1-TOP w5: MC2.153@4832.69,-1313.34 v1(4832.69,-1273.34)
  L6-BOT w5: v1@4832.69,-1275.34 4832.69,-1365.08 4867,-1399.39 4867,-1530.39 5236.22,-1899.61 6456.69,-1899.61 6968.5,-2411.42 6968.5,-2480.32 J15.33@7007.87,-2519.69
B25_L10N: J17.12 MC2.172 | length 3273.7
  L1-TOP w5: MC2.172@5009.86,-1558.65 5009.86,-1633.87 5049.21,-1673.23 7106.3,-1673.23 J17.12@7874.02,-2440.94
B25_L10P: J17.10 MC2.170 | length 3220.4
  L1-TOP w5: MC2.170@4990.17,-1558.65 4990.17,-1643.72 5039.37,-1692.91 7047.24,-1692.91 J17.10@7795.28,-2440.94
B25_L11N: J17.4 MC2.164 | length 3060.5
  L1-TOP w5: MC2.164@4931.12,-1558.65 4931.12,-1673.24 5009.84,-1751.97 6870.08,-1751.97 J17.4@7559.06,-2440.94
B25_L11P: J17.2 MC2.162 | length 3007.2
  L1-TOP w5: MC2.162@4911.43,-1558.65 4911.43,-1683.09 5000,-1771.65 6811.02,-1771.65 J17.2@7480.31,-2440.94
B25_L12N: J17.20 MC2.180 | length 3481.1
  L1-TOP w5: MC2.180@5088.6,-1558.65 5088.6,-1584.66 5098.43,-1594.49 7342.52,-1594.49 J17.20@8188.98,-2440.94
B25_L12P: J17.18 MC2.178 | length 3433.6
  L1-TOP w5: MC2.178@5068.91,-1558.65 5068.91,-1604.35 5078.74,-1614.17 7283.46,-1614.17 J17.18@8110.24,-2440.94
B25_L13N: J15.30 MC2.150 | length 2530
  L1-TOP w5: MC2.150@4793.32,-1558.65 4793.32,-1742.14 4940.94,-1889.76 6299.21,-1889.76 J15.30@6850.39,-2440.94
B25_L13P: J15.28 MC2.148 | length 2476.7
  L1-TOP w5: MC2.148@4773.64,-1558.65 4773.64,-1751.98 4931.1,-1909.45 6240.16,-1909.45 J15.28@6771.65,-2440.94
B25_L14N: J17.8 MC2.168 | length 3167.1
  L1-TOP w5: MC2.168@4970.49,-1558.65 4970.49,-1653.56 5029.53,-1712.6 6988.19,-1712.6 J17.8@7716.54,-2440.94
B25_L14P: J17.6 MC2.166 | length 3113.8
  L1-TOP w5: MC2.166@4950.8,-1558.65 4950.8,-1663.4 5019.69,-1732.28 6929.13,-1732.28 J17.6@7637.8,-2440.94
B25_L15N: J15.9 MC2.129 | length 2304.4
  L1-TOP w5: MC2.129@4596.47,-1313.34 v1(4596.47,-1273.34)
  L6-BOT w5: v1@4596.47,-1275.34 4596.47,-1325.19 4543.83,-1377.83 4543.83,-1561.55 5118.11,-2135.83 5748.03,-2135.83 6023.62,-2411.42 6023.62,-2480.32 J15.9@6062.99,-2519.69
B25_L15P: J15.7 MC2.127 | length 2329.9
  L1-TOP w5: MC2.127@4576.79,-1313.34 v1(4576.79,-1233.34)
  L6-BOT w5: v1@4576.79,-1235.34 4576.79,-1313.67 4525.65,-1364.8 4525.65,-1572.9 5108.27,-2155.51 5688.98,-2155.51 5944.88,-2411.42 5944.88,-2480.32 J15.7@5984.25,-2519.69
B25_L16N: J17.7 MC2.167 | length 3510.8
  L1-TOP w5: MC2.167@4970.49,-1313.34 v1(4970.49,-1233.34)
  L6-BOT w5: v1@4970.49,-1235.34 4970.49,-1322.49 5049.21,-1401.21 5049.21,-1505.91 5305.12,-1761.81 7027.56,-1761.81 7677.17,-2411.42 7677.17,-2480.32 J17.7@7716.54,-2519.69
B25_L16P: J17.5 MC2.165 | length 3377.5
  L1-TOP w5: MC2.165@4950.8,-1313.34 v1(4950.8,-1273.34)
  L6-BOT w5: v1@4950.8,-1275.34 4950.8,-1325.74 5029.53,-1404.46 5029.53,-1515.75 5295.28,-1781.5 6968.5,-1781.5 7598.43,-2411.42 7598.43,-2480.32 J17.5@7637.8,-2519.69
B25_L17N: J15.26 MC2.146 | length 2423.4
  L1-TOP w5: MC2.146@4753.95,-1558.65 4753.95,-1761.83 4921.26,-1929.13 6181.1,-1929.13 J15.26@6692.91,-2440.94
B25_L17P: J15.24 MC2.144 | length 2370.2
  L1-TOP w5: MC2.144@4734.27,-1558.65 4734.27,-1771.67 4911.42,-1948.82 6122.05,-1948.82 J15.24@6614.17,-2440.94
B25_L18N: J17.11 MC2.171 | length 3589
  L1-TOP w5: MC2.171@5009.86,-1313.34 v1(5009.86,-1233.34)
  L6-BOT w5: v1@5009.86,-1235.34 5009.86,-1305.86 5043.5,-1339.5 5063.95,-1339.5 5125.11,-1400.67 5125.11,-1453.85 5393.7,-1722.44 7145.67,-1722.44 7834.65,-2411.42 7834.65,-2480.32 J17.11@7874.02,-2519.69
B25_L18P: J17.9 MC2.169 | length 3484.1
  L1-TOP w5: MC2.169@4990.17,-1313.34 v1(4990.17,-1273.34)
  L6-BOT w5: v1@4990.17,-1275.34 4990.17,-1315.17 5068.9,-1393.9 5068.9,-1496.06 5314.96,-1742.13 7086.61,-1742.13 7755.91,-2411.42 7755.91,-2480.32 J17.9@7795.28,-2519.69
B25_L19N: J15.29 MC2.149 | length 2793.7
  L1-TOP w5: MC2.149@4793.32,-1313.34 v1(4793.32,-1273.34)
  L6-BOT w5: v1@4793.32,-1275.34 4793.32,-1389.25 4802,-1397.92 4802,-1524.44 5216.54,-1938.98 6338.58,-1938.98 6811.02,-2411.42 6811.02,-2480.32 J15.29@6850.39,-2519.69
B25_L19P: J15.27 MC2.147 | length 2820.4
  L1-TOP w5: MC2.147@4773.64,-1313.34 v1(4773.64,-1233.34)
  L6-BOT w5: v1@4773.64,-1235.34 4773.64,-1394.54 4780,-1400.9 4780,-1531.97 5206.69,-1958.66 6279.53,-1958.66 6732.28,-2411.42 6732.28,-2480.32 J15.27@6771.65,-2519.69
B25_L20N: J17.3 MC2.163 | length 3404.2
  L1-TOP w5: MC2.163@4931.12,-1313.34 v1(4931.12,-1233.34)
  L6-BOT w5: v1@4931.12,-1235.34 4931.12,-1331.62 4990.16,-1390.66 4990.16,-1505.91 5285.43,-1801.18 6909.45,-1801.18 7519.69,-2411.42 7519.69,-2480.31 J17.3@7559.06,-2519.69
B25_L20P: J17.1 MC2.161 | length 3270.9
  L1-TOP w5: MC2.161@4911.43,-1313.34 v1(4911.43,-1273.34)
  L6-BOT w5: v1@4911.43,-1275.34 4911.43,-1337.26 4966.93,-1392.75 4966.93,-1512.21 5275.59,-1820.87 6850.39,-1820.87 7440.94,-2411.42 7440.94,-2480.32 J17.1@7480.31,-2519.69
B25_L21N: J15.21 MC2.141 | length 2595.1
  L1-TOP w5: MC2.141@4714.58,-1313.34 v1(4714.58,-1273.34)
  L6-BOT w5: v1@4714.58,-1275.34 4714.58,-1373.24 4697,-1390.82 4697,-1537.55 5177.17,-2017.72 6102.36,-2017.72 6496.06,-2411.42 6496.06,-2480.32 J15.21@6535.43,-2519.69
B25_L21P: J15.19 MC2.139 | length 2637.9
  L1-TOP w5: MC2.139@4694.9,-1313.34 v1(4694.9,-1233.34)
  L6-BOT w5: v1@4694.9,-1235.34 4694.9,-1366.16 4657.84,-1403.22 4657.84,-1527.92 5167.32,-2037.4 6043.31,-2037.4 6417.32,-2411.42 6417.32,-2480.32 J15.19@6456.69,-2519.69
B25_L22N: J17.17 MC2.177 | length 3717.8
  L1-TOP w5: MC2.177@5068.91,-1313.34 v1(5068.91,-1273.34)
  L6-BOT w5: v1@5068.91,-1275.34 5172.98,-1275.34 5244,-1346.36 5244,-1484.16 5423.23,-1663.39 7322.83,-1663.39 8070.87,-2411.42 8070.87,-2480.32 J17.17@8110.24,-2519.69
B25_L22P: J17.15 MC2.175 | length 3748.8
  L1-TOP w5: MC2.175@5049.23,-1313.34 v1(5049.23,-1233.34)
  L6-BOT w5: v1@5049.23,-1235.34 5049.23,-1290.23 5056,-1297 5167.32,-1297 5222,-1351.68 5222,-1491.68 5413.39,-1683.07 7263.78,-1683.07 7992.13,-2411.42 7992.13,-2480.32 J17.15@8031.5,-2519.69
B25_L23N: J15.25 MC2.145 | length 2702
  L1-TOP w5: MC2.145@4753.95,-1313.34 v1(4753.95,-1273.34)
  L6-BOT w5: v1@4753.95,-1275.34 4753.95,-1386.01 4736,-1403.96 4736,-1517.5 5196.85,-1978.35 6220.47,-1978.35 6653.54,-2411.42 6653.54,-2480.32 J15.25@6692.91,-2519.69
B25_L23P: J15.23 MC2.143 | length 2728.1
  L1-TOP w5: MC2.143@4734.27,-1313.34 v1(4734.27,-1233.34)
  L6-BOT w5: v1@4734.27,-1235.34 4734.27,-1380.44 4717,-1397.71 4717,-1528.02 5187.01,-1998.03 6161.42,-1998.03 6574.8,-2411.42 6574.8,-2480.32 J15.23@6614.17,-2519.69
B25_L24N: J17.16 MC2.176 | length 3380.3
  L1-TOP w5: MC2.176@5049.23,-1558.65 5049.23,-1614.19 5068.9,-1633.86 7224.41,-1633.86 J17.16@8031.5,-2440.94
B25_L24P: J17.14 MC2.174 | length 3327
  L1-TOP w5: MC2.174@5029.54,-1558.65 5029.54,-1624.03 5059.06,-1653.54 7165.35,-1653.54 J17.14@7952.76,-2440.94
B25_T0U_N12: J15.36 MC2.156 | length 2689.9
  L1-TOP w5: MC2.156@4852.38,-1558.65 4852.38,-1712.61 4970.47,-1830.71 6476.38,-1830.71 J15.36@7086.61,-2440.94
B25_T1U_N12: J17.13 MC2.173 | length 3562.6
  L1-TOP w5: MC2.173@5029.54,-1313.34 v1(5029.54,-1273.34)
  L6-BOT w5: v1@5029.54,-1275.34 5029.54,-1300.54 5047,-1318 5068,-1318 5147.64,-1397.64 5147.64,-1446.85 5403.54,-1702.76 7204.72,-1702.76 7913.39,-2411.42 7913.39,-2480.32 J17.13@7952.76,-2519.69
B25_T2U_N12: J15.31 MC2.151 | length 2927
  L1-TOP w5: MC2.151@4813.01,-1313.34 v1(4813.01,-1233.34)
  L6-BOT w5: v1@4813.01,-1235.34 4813.01,-1382.45 4825.79,-1395.24 4825.79,-1518.71 5226.38,-1919.29 6397.64,-1919.29 6889.76,-2411.42 6889.76,-2480.32 J15.31@6929.13,-2519.69
B25_T3U_N12: J17.19 MC2.179 | length 3833.4
  L1-TOP w5: MC2.179@5088.6,-1313.34 v1(5088.6,-1233.34)
  L6-BOT w5: v1@5088.6,-1235.34 5142.61,-1235.34 5162.5,-1235.34 5268,-1340.83 5268,-1478.63 5433.07,-1643.7 7381.89,-1643.7 8149.61,-2411.42 8149.61,-2480.32 J17.19@8188.98,-2519.69
B44_L1N: J9.26 MC2.26 | length 2133
  L1-TOP w5: J9.26@1496.06,-2440.95 1958.66,-1978.35 2903.54,-1978.35 3179.15,-1702.74 MC2.26@3179.15,-1558.65
B44_L1P: J9.24 MC2.24 | length 2186.2
  L1-TOP w5: J9.24@1417.32,-2440.95 1899.61,-1958.66 2893.7,-1958.66 3159.46,-1692.9 MC2.24@3159.46,-1558.65
B44_L2N: J9.5 MC2.5 | length 2921.1
  L1-TOP w5: MC2.5@2982.3,-1313.34 v1(2982.3,-1273.34)
  L6-BOT w5: J9.5@708.66,-2519.69 748.03,-2480.32 748.03,-2411.42 1545.28,-1614.17 2633.83,-1614.17 2804,-1444 2804,-1368.53 2855.53,-1317 2953.32,-1317 2982.3,-1288.02 v1@2982.3,-1275.34
B44_L2P: J9.3 MC2.3 | length 3062.1
  L1-TOP w5: MC2.3@2962.61,-1313.34 v1(2962.61,-1233.34)
  L6-BOT w5: J9.3@629.92,-2519.69 669.29,-2480.32 669.29,-2411.42 1486.22,-1594.49 2627.95,-1594.49 2784,-1438.44 2784,-1354.13 2838.61,-1299.52 2945.59,-1299.52 2962.61,-1282.5 v1@2962.61,-1235.34
B44_L3N: J9.10 MC2.10 | length 2559.3
  L1-TOP w5: J9.10@866.14,-2440.94 1486.22,-1820.87 2824.8,-1820.87 3021.67,-1624 MC2.10@3021.67,-1558.65
B44_L3P: J9.8 MC2.8 | length 2612.6
  L1-TOP w5: J9.8@787.4,-2440.94 1427.17,-1801.18 2814.96,-1801.18 3001.98,-1614.16 MC2.8@3001.98,-1558.65
B44_L4N: J9.17 MC2.17 | length 2551.1
  L1-TOP w5: MC2.17@3100.41,-1313.34 v1(3100.41,-1273.34)
  L6-BOT w5: J9.17@1181.1,-2519.69 1220.47,-2480.32 1220.47,-2411.42 1899.61,-1732.28 2692.72,-1732.28 2879,-1546 2879,-1535 2918.74,-1495.26 2930.94,-1495.26 3004.6,-1421.6 3004.6,-1403.4 3100.41,-1307.59 v1@3100.41,-1275.34
B44_L4P: J9.15 MC2.15 | length 2684.6
  L1-TOP w5: MC2.15@3080.72,-1313.34 v1(3080.72,-1233.34)
  L6-BOT w5: J9.15@1102.36,-2519.69 1141.73,-2480.32 1141.73,-2411.42 1840.55,-1712.6 2681.4,-1712.6 2851,-1543 2851,-1535 2907.46,-1478.54 2921.44,-1478.54 2978.92,-1421.06 2978.92,-1404.08 3080.72,-1302.28 v1@3080.72,-1235.34
B44_L5N: J9.22 MC2.22 | length 2239.5
  L1-TOP w5: J9.22@1338.58,-2440.95 1840.55,-1938.98 2883.86,-1938.98 3139.78,-1683.06 MC2.22@3139.78,-1558.65
B44_L5P: J9.20 MC2.20 | length 2292.8
  L1-TOP w5: J9.20@1259.84,-2440.95 1781.5,-1919.29 2874.02,-1919.29 3120.09,-1673.21 MC2.20@3120.09,-1558.65
B44_L6N: J9.18 MC2.18 | length 2346.1
  L1-TOP w5: J9.18@1181.1,-2440.95 1722.44,-1899.61 2864.17,-1899.61 3100.41,-1663.37 MC2.18@3100.41,-1558.65
B44_L6P: J9.16 MC2.16 | length 2399.4
  L1-TOP w5: J9.16@1102.36,-2440.95 1663.39,-1879.92 2854.33,-1879.92 3080.72,-1653.53 MC2.16@3080.72,-1558.65
B44_L7N: J9.9 MC2.9 | length 2769.6
  L1-TOP w5: MC2.9@3021.67,-1313.34 v1(3021.67,-1273.34)
  L6-BOT w5: J9.9@866.14,-2519.69 905.51,-2480.32 905.51,-2411.42 1663.39,-1653.54 2652.46,-1653.54 2882.25,-1423.75 2882.25,-1410.81 2940.56,-1352.5 2962.8,-1352.5 3021.67,-1293.63 v1@3021.67,-1275.34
